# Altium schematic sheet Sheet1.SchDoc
size A4
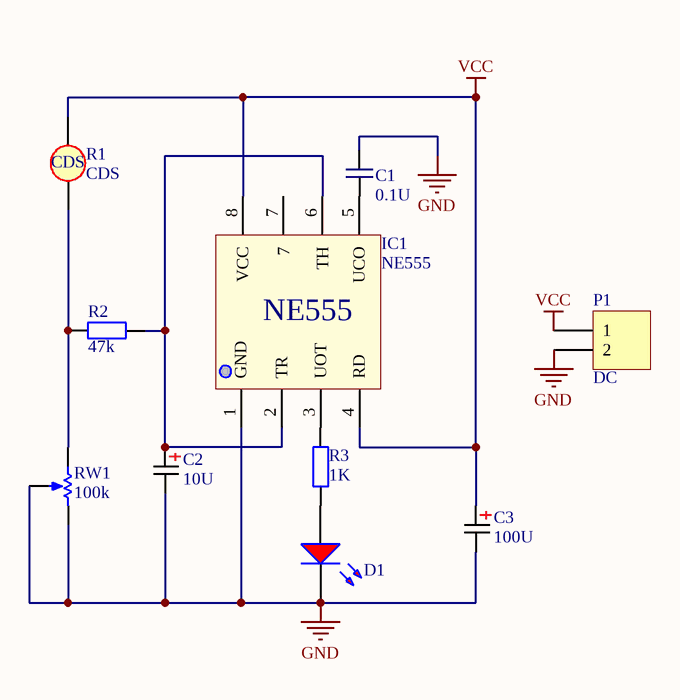
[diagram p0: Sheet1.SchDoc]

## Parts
C1  0.1U  [RAD0.1]
C2  10U  [CF0.1]
C3  100U  [CF0.1]
D1  LED0  [LED]  (value not drawn)
IC1  NE555  [DIP-8]
P1  DC  [HDR1X2]
R1  CDS  [CDS]
R2  47k  [AXIAL-0.3]
R3  1K  [AXIAL-0.3]
RW1  100k  [RW1]

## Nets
GND: C1.2 C2.2 C3.2 D1.2(K) IC1.1(GND) P1.2 RW1.2(TAP) RW1.3(BOT)
VCC: C3.1 IC1.4(RD) IC1.8(VCC) P1.1 R1.1
NetC1_1: C1.1 IC1.5(UCO)
NetC2_1: C2.1 IC1.2(TR) IC1.6(TH) R2.2
NetD1_1: D1.1(A) R3.1
NetIC1_3: IC1.3(UOT) R3.2
NetR1_2: R1.2 R2.1 RW1.1(TOP)

Not connected (* = marked no-connect by the designer): IC1 7

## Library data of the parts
C1 = Cap
C2 C3 = Cap Pol
P1 = Header 2: Header, 2-Pin
R2 = Res: Resistor; Value: 1K
R3 = Res: Resistor
RW1 = RW1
